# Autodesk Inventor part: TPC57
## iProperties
Shininess: 64.0
Length Units: 11272
Angle Units: 11279
Time Units: 11290
Mass Units: 11286
Length Display Precision: 3
Angle Display Precision: 2
Compacted: True
Part Number: TPC57
Document SubType Name: Modeling
Created: 2004-08
Designer: Lori
Manufacturer: Standard
Standards Organization: Custom
Density: 0.0
Volumn: 0.0
Area: 0.0
PropertySet Name: Model Information
Control State: 0
Master: False
Checked Out: False
Author: Lori
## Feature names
1. Base1
